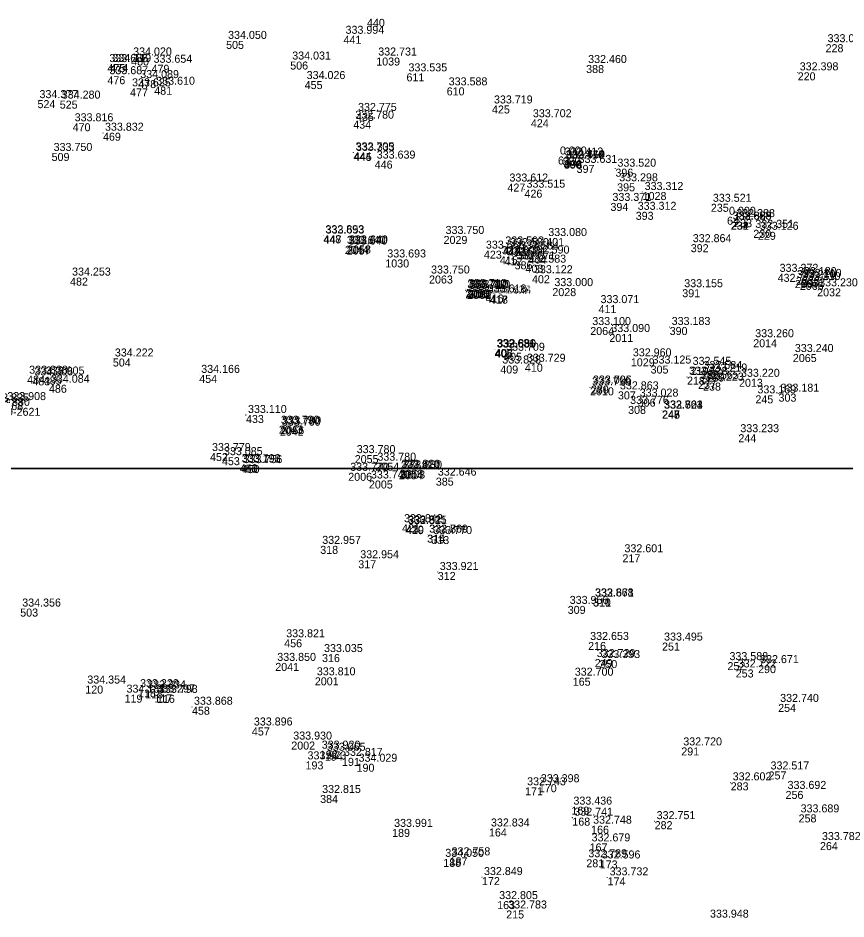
# Model space of a CAD drawing. Extents: x -829398 to -819400, y -1074439 to -1067977.
# Drawn here: x -819793.7 to -819669.5, y -1073067.5 to -1072932.5 of the extents above; entities that cross this region are included whole.
import ezdxf

# ---------------------------------------------------------------- set-up
doc = ezdxf.new("R2010")
doc.units = 0
for name, color, linetype in [('Vrstva 60', 7, 'Continuous'), ('Vrstva 61', 7, 'Continuous'), ('Čísla bodů_doměření_2012', 7, 'Continuous')]:
    doc.layers.add(name, color=color, linetype=linetype)

# ---------------------------------------------------------------- blocks, each defined once
blk = doc.blocks.new('BOD')
at = {"layer": 'Čísla bodů_doměření_2012'}
for p, q in [((-0.15, 0), (0.15, 0)), ((0, -0.15), (0, 0.15))]:
    blk.add_line(p, q, dxfattribs=at)

msp = doc.modelspace()

# ---------------------------------------------------------------- linework, layer by layer
at = {"layer": 'Vrstva 61'}
for points in [[(-819400, -1072500), (-820100, -1072500), (-820100, -1073000), (-819400, -1073000)], [(-819500, -1073000), (-820200, -1073000), (-820200, -1073500), (-819500, -1073500)]]:
    msp.add_lwpolyline(points, close=True, dxfattribs=at)

# ---------------------------------------------------------------- block references
at = {"layer": 'Vrstva 60', "xscale": 0.010000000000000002, "yscale": 0.010000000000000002}
for p in [(-819741.346, -1072932.627), (-819762.463, -1072935.941), (-819744.858, -1072935.172), (-819672.591, -1072936.433), (-819776.698, -1072938.42), (-819739.955, -1072938.429), (-819780.255, -1072939.412), (-819779.8, -1072939.386), (-819773.639, -1072939.515), (-819752.848, -1072939.032), (-819708.487, -1072939.554), (-819780.249, -1072941.229), (-819735.421, -1072940.802), (-819676.772, -1072940.648), (-819775.633, -1072941.811), (-819750.686, -1072941.956), (-819776.86, -1072943.052), (-819773.234, -1072942.806), (-819729.392, -1072942.904), (-819790.739, -1072944.814), (-819787.397, -1072944.888), (-819742.985, -1072946.734), (-819722.609, -1072945.612), (-819743.397, -1072947.889), (-819716.771, -1072947.68), (-819785.465, -1072948.283), (-819780.917, -1072949.7), (-819788.618, -1072952.733), (-819743.353, -1072952.639), (-819743.3, -1072952.717), (-819712.715, -1072953.265), (-819712.024, -1072953.42), (-819740.183, -1072953.876), (-819711.868, -1072953.87), (-819711.807, -1072953.884), (-819711.756, -1072953.81), (-819709.919, -1072954.521), (-819704.098, -1072955.088), (-819720.285, -1072957.317), (-819703.836, -1072957.279), (-819717.73, -1072958.233), (-819700.017, -1072958.584), (-819704.842, -1072960.223), (-819701.058, -1072961.551), (-819689.79, -1072960.351), (-819687.369, -1072962.295), (-819686.828, -1072963.021), (-819686.287, -1072962.646), (-819686.794, -1072963.035), (-819686.775, -1072963.04), (-819683.429, -1072964.253), (-819747.877, -1072965.058), (-819747.839, -1072965.109), (-819729.86, -1072965.17), (-819714.466, -1072965.484), (-819682.74, -1072964.549), (-819744.65, -1072966.66), (-819744.38, -1072966.76), (-819744.32, -1072966.59), (-819720.901, -1072966.742), (-819720.186, -1072966.997), (-819692.806, -1072966.404), (-819723.815, -1072967.371), (-819721.42, -1072968.207), (-819720.727, -1072968.375), (-819718.667, -1072967.497), (-819717.087, -1072968.111), (-819738.597, -1072968.692), (-819719.211, -1072968.97), (-819717.585, -1072969.471), (-819732.04, -1072971.1), (-819716.607, -1072971.06), (-819679.781, -1072970.848), (-819785.854, -1072971.41), (-819677.2, -1072971.78), (-819677.04, -1072971.34), (-819676.46, -1072972.06), (-819676.3, -1072971.61), (-819726.6, -1072973.31), (-819726.53, -1072973.12), (-819726.31, -1072973.41), (-819726.25, -1072973.21), (-819725.98, -1072973.29), (-819713.55, -1072972.99), (-819694.078, -1072973.155), (-819673.86, -1072973.02), (-819723.545, -1072973.945), (-819722.94, -1072974.144), (-819722.882, -1072974.106), (-819706.629, -1072975.537), (-819707.87, -1072978.82), (-819695.967, -1072978.815), (-819705.01, -1072979.87), (-819683.44, -1072980.65), (-819722.198, -1072982.123), (-819722.173, -1072982.212), (-819722.095, -1072982.155), (-819720.785, -1072982.678), (-819677.5, -1072982.87), (-819779.439, -1072983.537), (-819721.356, -1072984.59), (-819717.674, -1072984.324), (-819701.786, -1072983.515), (-819698.823, -1072984.596), (-819692.823, -1072984.788), (-819691.196, -1072985.418), (-819690.43, -1072985.79), (-819792.288, -1072986.117), (-819791.507, -1072986.368), (-819789.796, -1072986.24), (-819766.489, -1072985.996), (-819693.367, -1072986.263), (-819691.703, -1072986.887), (-819690.958, -1072987.149), (-819685.57, -1072986.58), (-819789.021, -1072987.471), (-819707.9, -1072987.86), (-819707.768, -1072987.595), (-819707.768, -1072987.596), (-819703.72, -1072988.466), (-819700.757, -1072989.547), (-819683.111, -1072989.062), (-819679.647, -1072988.808), (-819702.198, -1072990.647), (-819697.121, -1072991.364), (-819697.12, -1072991.316), (-819697.084, -1072991.342), (-819759.48, -1072992.005), (-819754.55, -1072993.61), (-819754.4, -1072993.92), (-819754.32, -1072993.7), (-819685.669, -1072994.884), (-819764.874, -1072997.708), (-819743.18, -1072998.02), (-819763.086, -1072998.326), (-819760.403, -1072999.435), (-819760.394, -1072999.379), (-819740.08, -1072999.15), (-819760.133, -1072999.517), (-819744.15, -1073000.67), (-819744.15, -1073000.67), (-819736.56, -1073000.44), (-819736.56, -1073000.44), (-819736.48, -1073000.22), (-819736.48, -1073000.22), (-819736.19, -1073000.32), (-819736.19, -1073000.32), (-819741.05, -1073001.82), (-819741.05, -1073001.82), (-819731.024, -1073001.391), (-819731.024, -1073001.391), (-819736.085, -1073008.37), (-819736.085, -1073008.37), (-819735.503, -1073008.571), (-819735.503, -1073008.571), (-819735.482, -1073008.663), (-819735.482, -1073008.663), (-819732.329, -1073009.933), (-819732.329, -1073009.933), (-819732.299, -1073009.952), (-819732.299, -1073009.952), (-819731.693, -1073010.151), (-819731.693, -1073010.151), (-819748.351, -1073011.623), (-819748.351, -1073011.623), (-819703.042, -1073012.879), (-819703.042, -1073012.879), (-819742.65, -1073013.778), (-819742.65, -1073013.778), (-819730.733, -1073015.538), (-819730.733, -1073015.538), (-819707.48, -1073019.493), (-819707.48, -1073019.493), (-819707.43, -1073019.513), (-819707.43, -1073019.513), (-819793.321, -1073021.015), (-819793.321, -1073021.015), (-819711.249, -1073020.618), (-819711.249, -1073020.618), (-819753.75, -1073025.621), (-819753.75, -1073025.621), (-819708.184, -1073026.021), (-819708.184, -1073026.021), (-819697.105, -1073026.114), (-819697.105, -1073026.114), (-819748.079, -1073027.837), (-819748.079, -1073027.837), (-819755.09, -1073029.16), (-819755.09, -1073029.16), (-819707.202, -1073028.587), (-819707.202, -1073028.587), (-819706.499, -1073028.733), (-819706.499, -1073028.733), (-819687.304, -1073029.045), (-819687.304, -1073029.045), (-819686.064, -1073030.141), (-819686.064, -1073030.141), (-819682.712, -1073029.494), (-819682.712, -1073029.494), (-819749.16, -1073031.32), (-819749.16, -1073031.32), (-819710.497, -1073031.378), (-819710.497, -1073031.378), (-819783.568, -1073032.556), (-819783.568, -1073032.556), (-819775.659, -1073033.101), (-819775.659, -1073033.101), (-819777.685, -1073033.916), (-819777.685, -1073033.916), (-819774.586, -1073033.288), (-819774.586, -1073033.288), (-819773.225, -1073033.893), (-819773.225, -1073033.893), (-819772.827, -1073033.95), (-819772.827, -1073033.95), (-819767.574, -1073035.732), (-819767.574, -1073035.732), (-819679.701, -1073035.307), (-819679.701, -1073035.307), (-819758.599, -1073038.841), (-819758.599, -1073038.841), (-819752.69, -1073040.95), (-819752.69, -1073040.95), (-819748.43, -1073042.311), (-819748.43, -1073042.311), (-819747.654, -1073042.624), (-819747.654, -1073042.624), (-819694.225, -1073041.828), (-819694.225, -1073041.828), (-819750.557, -1073043.919), (-819750.557, -1073043.919), (-819745.088, -1073043.395), (-819745.088, -1073043.395), (-819742.904, -1073044.272), (-819742.904, -1073044.272), (-819681.145, -1073045.428), (-819681.145, -1073045.428), (-819717.636, -1073047.805), (-819717.636, -1073047.805), (-819715.58, -1073047.342), (-819715.58, -1073047.342), (-819686.821, -1073047.063), (-819686.821, -1073047.063), (-819748.364, -1073048.957), (-819748.364, -1073048.957), (-819678.592, -1073048.348), (-819678.592, -1073048.348), (-819710.691, -1073050.7), (-819710.691, -1073050.7), (-819676.638, -1073051.866), (-819676.638, -1073051.866), (-819710.558, -1073052.355), (-819710.558, -1073052.355), (-819698.217, -1073052.88), (-819698.217, -1073052.88), (-819737.574, -1073054.039), (-819737.574, -1073054.039), (-819723.055, -1073053.977), (-819723.055, -1073053.977), (-819707.743, -1073053.56), (-819707.743, -1073053.56), (-819673.434, -1073056.016), (-819673.434, -1073056.016), (-819707.97, -1073056.213), (-819707.97, -1073056.213), (-819729.899, -1073058.527), (-819729.899, -1073058.527), (-819728.958, -1073058.296), (-819728.958, -1073058.296), (-819708.456, -1073058.591), (-819708.456, -1073058.591), (-819706.453, -1073058.769), (-819706.453, -1073058.769), (-819724.1, -1073061.259), (-819724.1, -1073061.259), (-819705.267, -1073061.299), (-819705.267, -1073061.299), (-819721.825, -1073064.86), (-819721.825, -1073064.86), (-819720.469, -1073066.267), (-819720.469, -1073066.267)]:
    msp.add_blockref('BOD', p, dxfattribs=at)

# ---------------------------------------------------------------- texts
at = {"layer": 'Vrstva 60'}
for s, p in [('440', (-819741.346, -1072933.827)), ('505', (-819762.463, -1072937.141)), ('441', (-819744.858, -1072936.372)), ('228', (-819672.591, -1072937.633)), ('480', (-819776.698, -1072939.62)), ('1039', (-819739.955, -1072939.629)), ('475', (-819780.255, -1072940.612)), ('474', (-819779.8, -1072940.586)), ('479', (-819773.639, -1072940.715)), ('506', (-819752.848, -1072940.232)), ('388', (-819708.487, -1072940.754)), ('476', (-819780.249, -1072942.429)), ('611', (-819735.421, -1072942.002)), ('220', (-819676.772, -1072941.848)), ('478', (-819775.633, -1072943.011)), ('455', (-819750.686, -1072943.156)), ('477', (-819776.86, -1072944.252)), ('481', (-819773.234, -1072944.006)), ('610', (-819729.392, -1072944.104)), ('524', (-819790.739, -1072946.014)), ('525', (-819787.397, -1072946.088)), ('435', (-819742.985, -1072947.934)), ('425', (-819722.609, -1072946.812)), ('434', (-819743.397, -1072949.089)), ('424', (-819716.771, -1072948.88)), ('470', (-819785.465, -1072949.483)), ('469', (-819780.917, -1072950.9)), ('509', (-819788.618, -1072953.933)), ('444', (-819743.353, -1072953.839)), ('445', (-819743.3, -1072953.917)), ('63', (-819712.715, -1072954.465)), ('389', (-819712.024, -1072954.62)), ('446', (-819740.183, -1072955.076)), ('400', (-819711.868, -1072955.07)), ('399', (-819711.807, -1072955.084)), ('398', (-819711.756, -1072955.01)), ('397', (-819709.919, -1072955.721)), ('396', (-819704.098, -1072956.288)), ('427', (-819720.285, -1072958.517)), ('395', (-819703.836, -1072958.479)), ('426', (-819717.73, -1072959.433)), ('1028', (-819700.017, -1072959.784)), ('394', (-819704.842, -1072961.423)), ('393', (-819701.058, -1072962.751)), ('235', (-819689.79, -1072961.551)), ('64', (-819687.369, -1072963.495)), ('234', (-819686.828, -1072964.221)), ('232', (-819686.794, -1072964.235)), ('231', (-819686.775, -1072964.24)), ('233', (-819686.287, -1072963.846)), ('230', (-819683.429, -1072965.453)), ('448', (-819747.877, -1072966.258)), ('447', (-819747.839, -1072966.309)), ('2029', (-819729.86, -1072966.37)), ('401', (-819714.466, -1072966.684)), ('229', (-819682.74, -1072965.749)), ('2044', (-819744.65, -1072967.86)), ('2057', (-819744.38, -1072967.96)), ('2058', (-819744.32, -1072967.79)), ('414', (-819720.901, -1072967.942)), ('413', (-819720.186, -1072968.197)), ('392', (-819692.806, -1072967.604)), ('423', (-819723.815, -1072968.571)), ('415', (-819721.42, -1072969.407)), ('412', (-819720.727, -1072969.575)), ('387', (-819718.667, -1072968.697)), ('404', (-819717.087, -1072969.311)), ('1030', (-819738.597, -1072969.892)), ('386', (-819719.211, -1072970.17)), ('403', (-819717.585, -1072970.671)), ('2063', (-819732.04, -1072972.3)), ('402', (-819716.607, -1072972.26)), ('432', (-819679.781, -1072972.048)), ('482', (-819785.854, -1072972.61)), ('2067', (-819677.2, -1072972.98)), ('2030', (-819677.04, -1072972.54)), ('2066', (-819676.46, -1072973.26)), ('2031', (-819676.3, -1072972.81)), ('2060', (-819726.6, -1072974.51)), ('2059', (-819726.53, -1072974.32)), ('2061', (-819726.31, -1072974.61)), ('2062', (-819726.25, -1072974.41)), ('2007', (-819725.98, -1072974.49)), ('2028', (-819713.55, -1072974.19)), ('391', (-819694.078, -1072974.355)), ('2032', (-819673.86, -1072974.22)), ('416', (-819723.545, -1072975.145)), ('417', (-819722.94, -1072975.344)), ('418', (-819722.882, -1072975.306)), ('411', (-819706.629, -1072976.737)), ('2064', (-819707.87, -1072980.02)), ('390', (-819695.967, -1072980.015)), ('2011', (-819705.01, -1072981.07)), ('2014', (-819683.44, -1072981.85)), ('408', (-819722.198, -1072983.323)), ('406', (-819722.173, -1072983.412)), ('407', (-819722.095, -1072983.355)), ('405', (-819720.785, -1072983.878)), ('2065', (-819677.5, -1072984.07)), ('504', (-819779.439, -1072984.737)), ('409', (-819721.356, -1072985.79)), ('410', (-819717.674, -1072985.524)), ('1029', (-819701.786, -1072984.715)), ('305', (-819698.823, -1072985.796)), ('219', (-819692.823, -1072985.988)), ('236', (-819691.196, -1072986.618)), ('239', (-819690.43, -1072986.99)), ('484', (-819792.288, -1072987.317)), ('483', (-819791.507, -1072987.568)), ('485', (-819789.796, -1072987.44)), ('454', (-819766.489, -1072987.196)), ('218', (-819693.367, -1072987.463)), ('237', (-819691.703, -1072988.087)), ('238', (-819690.958, -1072988.349)), ('2013', (-819685.57, -1072987.78)), ('486', (-819789.021, -1072988.671)), ('2010', (-819707.9, -1072989.06)), ('280', (-819707.768, -1072988.795)), ('279', (-819707.768, -1072988.796)), ('307', (-819703.72, -1072989.666)), ('306', (-819700.757, -1072990.747)), ('245', (-819683.111, -1072990.262)), ('303', (-819679.647, -1072990.008)), ('5799-2621', (-819797.973, -1072992.128)), ('468', (-819795.563, -1072991.27)), ('308', (-819702.198, -1072991.847)), ('248', (-819697.121, -1072992.564)), ('247', (-819697.12, -1072992.516)), ('246', (-819697.084, -1072992.542)), ('433', (-819759.48, -1072993.205)), ('2043', (-819754.55, -1072994.81)), ('2042', (-819754.4, -1072995.12)), ('2056', (-819754.32, -1072994.9)), ('244', (-819685.669, -1072996.084)), ('452', (-819764.874, -1072998.908)), ('2055', (-819743.18, -1072999.22)), ('453', (-819763.086, -1072999.526)), ('451', (-819760.403, -1073000.635)), ('449', (-819760.394, -1073000.579)), ('2054', (-819740.08, -1073000.35)), ('2054', (-819740.08, -1073000.35)), ('450', (-819760.133, -1073000.717)), ('2006', (-819744.15, -1073001.87)), ('2004', (-819736.56, -1073001.64)), ('2053', (-819736.48, -1073001.42)), ('2003', (-819736.19, -1073001.52)), ('2005', (-819741.05, -1073003.02)), ('385', (-819731.024, -1073002.591)), ('421', (-819736.085, -1073009.57)), ('420', (-819735.503, -1073009.771)), ('419', (-819735.482, -1073009.863)), ('315', (-819732.329, -1073011.133)), ('314', (-819732.299, -1073011.152)), ('313', (-819731.693, -1073011.351)), ('318', (-819748.351, -1073012.823)), ('217', (-819703.042, -1073014.079)), ('317', (-819742.65, -1073014.978)), ('312', (-819730.733, -1073016.738)), ('310', (-819707.48, -1073020.693)), ('311', (-819707.43, -1073020.713)), ('503', (-819793.321, -1073022.215)), ('309', (-819711.249, -1073021.818)), ('456', (-819753.75, -1073026.821)), ('216', (-819708.184, -1073027.221)), ('251', (-819697.105, -1073027.314)), ('316', (-819748.079, -1073029.037)), ('2041', (-819755.09, -1073030.36)), ('249', (-819707.202, -1073029.787)), ('250', (-819706.499, -1073029.933)), ('252', (-819687.304, -1073030.245)), ('253', (-819686.064, -1073031.341)), ('290', (-819682.712, -1073030.694)), ('2001', (-819749.16, -1073032.52)), ('165', (-819710.497, -1073032.578)), ('120', (-819783.568, -1073033.756)), ('118', (-819775.659, -1073034.301)), ('119', (-819777.685, -1073035.116)), ('115', (-819774.586, -1073034.488)), ('117', (-819773.225, -1073035.093)), ('116', (-819772.827, -1073035.15)), ('458', (-819767.574, -1073036.932)), ('254', (-819679.701, -1073036.507)), ('457', (-819758.599, -1073040.041)), ('2002', (-819752.69, -1073042.15)), ('192', (-819748.43, -1073043.511)), ('194', (-819747.654, -1073043.824)), ('291', (-819694.225, -1073043.028)), ('193', (-819750.557, -1073045.119)), ('191', (-819745.088, -1073044.595)), ('190', (-819742.904, -1073045.472)), ('257', (-819681.145, -1073046.628)), ('171', (-819717.636, -1073049.005)), ('170', (-819715.58, -1073048.542)), ('283', (-819686.821, -1073048.263)), ('384', (-819748.364, -1073050.157)), ('256', (-819678.592, -1073049.548)), ('169', (-819710.691, -1073051.9)), ('258', (-819676.638, -1073053.066)), ('168', (-819710.558, -1073053.555)), ('282', (-819698.217, -1073054.08)), ('189', (-819737.574, -1073055.239)), ('164', (-819723.055, -1073055.177)), ('166', (-819707.743, -1073054.76)), ('167', (-819707.97, -1073057.413)), ('264', (-819673.434, -1073057.216)), ('188', (-819729.899, -1073059.727)), ('187', (-819728.958, -1073059.496)), ('281', (-819708.456, -1073059.791)), ('173', (-819706.453, -1073059.969)), ('172', (-819724.1, -1073062.459)), ('174', (-819705.267, -1073062.499)), ('163', (-819721.825, -1073066.06)), ('215', (-819720.469, -1073067.467))]:
    msp.add_text(s, height=1.2, dxfattribs=at).set_placement(p)
at = {"layer": 'Vrstva 61'}
for s, p in [('334.050', (-819762.163, -1072935.641)), ('333.994', (-819744.558, -1072934.872)), ('333.058', (-819672.291, -1072936.133)), ('334.020', (-819776.398, -1072938.12)), ('332.731', (-819739.655, -1072938.129)), ('333.686', (-819779.955, -1072939.112)), ('334.119', (-819779.5, -1072939.086)), ('333.654', (-819773.339, -1072939.215)), ('334.031', (-819752.548, -1072938.732)), ('332.460', (-819708.187, -1072939.254)), ('333.687', (-819779.949, -1072940.929)), ('333.535', (-819735.121, -1072940.502)), ('332.398', (-819676.472, -1072940.348)), ('334.089', (-819775.333, -1072941.511)), ('333.610', (-819772.934, -1072942.506)), ('334.026', (-819750.386, -1072941.656)), ('333.588', (-819729.092, -1072942.604)), ('333.625', (-819776.56, -1072942.752)), ('334.377', (-819790.439, -1072944.514)), ('334.280', (-819787.097, -1072944.588)), ('333.719', (-819722.309, -1072945.312)), ('332.775', (-819742.685, -1072946.434)), ('333.816', (-819785.165, -1072947.983)), ('332.780', (-819743.097, -1072947.589)), ('333.702', (-819716.471, -1072947.38)), ('333.832', (-819780.617, -1072949.4)), ('333.750', (-819788.318, -1072952.433)), ('332.705', (-819743.053, -1072952.339)), ('333.333', (-819743, -1072952.417)), ('0.000', (-819712.415, -1072952.965)), ('332.412', (-819711.724, -1072953.12)), ('333.639', (-819739.883, -1072953.576)), ('332.475', (-819711.568, -1072953.57)), ('332.754', (-819711.507, -1072953.584)), ('333.619', (-819711.456, -1072953.51)), ('333.631', (-819709.619, -1072954.221)), ('333.520', (-819703.798, -1072954.788)), ('333.612', (-819719.985, -1072957.017)), ('333.298', (-819703.536, -1072956.979)), ('333.515', (-819717.43, -1072957.933)), ('333.312', (-819699.717, -1072958.284)), ('333.371', (-819704.542, -1072959.923)), ('333.521', (-819689.49, -1072960.051)), ('333.312', (-819700.758, -1072961.251)), ('0.000', (-819687.069, -1072961.995)), ('333.658', (-819686.528, -1072962.721)), ('332.825', (-819686.494, -1072962.735)), ('332.389', (-819686.475, -1072962.74)), ('332.388', (-819685.987, -1072962.346)), ('332.351', (-819683.129, -1072963.953)), ('332.893', (-819747.577, -1072964.758)), ('333.653', (-819747.539, -1072964.809)), ('333.750', (-819729.56, -1072964.87)), ('333.080', (-819714.166, -1072965.184)), ('333.126', (-819682.44, -1072964.249)), ('333.640', (-819744.35, -1072966.36)), ('333.640', (-819744.08, -1072966.46)), ('333.640', (-819744.02, -1072966.29)), ('333.592', (-819720.601, -1072966.442)), ('332.580', (-819719.886, -1072966.697)), ('332.864', (-819692.506, -1072966.104)), ('333.666', (-819723.515, -1072967.071)), ('333.603', (-819721.12, -1072967.907)), ('332.574', (-819720.427, -1072968.075)), ('332.564', (-819718.367, -1072967.197)), ('332.590', (-819716.787, -1072967.811)), ('333.693', (-819738.297, -1072968.392)), ('332.571', (-819718.911, -1072968.67)), ('332.583', (-819717.285, -1072969.171)), ('333.750', (-819731.74, -1072970.8)), ('333.122', (-819716.307, -1072970.76)), ('333.272', (-819679.481, -1072970.548)), ('334.253', (-819785.554, -1072971.11)), ('333.210', (-819676.9, -1072971.48)), ('333.180', (-819676.74, -1072971.04)), ('333.210', (-819676.16, -1072971.76)), ('333.210', (-819676, -1072971.31)), ('333.710', (-819726.3, -1072973.01)), ('333.710', (-819726.23, -1072972.82)), ('333.710', (-819726.01, -1072973.11)), ('333.710', (-819725.95, -1072972.91)), ('333.710', (-819725.68, -1072972.99)), ('333.618', (-819723.245, -1072973.645)), ('333.000', (-819713.25, -1072972.69)), ('333.155', (-819693.778, -1072972.855)), ('333.230', (-819673.56, -1072972.72)), ('333.712', (-819722.64, -1072973.844)), ('332.538', (-819722.582, -1072973.806)), ('333.071', (-819706.329, -1072975.237)), ('333.100', (-819707.57, -1072978.52)), ('333.183', (-819695.667, -1072978.515)), ('333.090', (-819704.71, -1072979.57)), ('333.260', (-819683.14, -1072980.35)), ('332.631', (-819721.898, -1072981.823)), ('333.686', (-819721.873, -1072981.912)), ('332.880', (-819721.795, -1072981.855)), ('333.709', (-819720.485, -1072982.378)), ('333.240', (-819677.2, -1072982.57)), ('334.222', (-819779.139, -1072983.237)), ('333.828', (-819721.056, -1072984.29)), ('333.729', (-819717.374, -1072984.024)), ('332.960', (-819701.486, -1072983.215)), ('333.125', (-819698.523, -1072984.296)), ('332.545', (-819692.523, -1072984.488)), ('333.838', (-819791.988, -1072985.817)), ('334.166', (-819766.189, -1072985.696)), ('332.584', (-819690.896, -1072985.118)), ('333.219', (-819690.13, -1072985.49)), ('334.306', (-819791.207, -1072986.068)), ('333.905', (-819789.496, -1072985.94)), ('334.084', (-819788.721, -1072987.171)), ('332.528', (-819693.067, -1072985.963)), ('332.565', (-819691.403, -1072986.587)), ('333.223', (-819690.658, -1072986.849)), ('333.220', (-819685.27, -1072986.28)), ('333.710', (-819707.6, -1072987.56)), ('333.026', (-819707.468, -1072987.295)), ('333.705', (-819707.468, -1072987.296)), ('332.863', (-819703.42, -1072988.166)), ('333.181', (-819679.347, -1072988.508)), ('333.908', (-819795.263, -1072989.77)), ('333.028', (-819700.457, -1072989.247)), ('333.169', (-819682.811, -1072988.762)), ('333.835', (-819797.812, -1072989.979)), ('333.880', (-819797.673, -1072990.628)), ('333.776', (-819701.898, -1072990.347)), ('333.723', (-819696.821, -1072991.064)), ('332.861', (-819696.82, -1072991.016)), ('332.504', (-819696.784, -1072991.042)), ('333.110', (-819759.18, -1072991.705)), ('333.790', (-819754.25, -1072993.31)), ('333.760', (-819754.1, -1072993.62)), ('333.780', (-819754.02, -1072993.4)), ('333.233', (-819685.369, -1072994.584)), ('333.779', (-819764.574, -1072997.408)), ('333.780', (-819742.88, -1072997.72)), ('333.085', (-819762.786, -1072998.026)), ('333.195', (-819760.103, -1072999.135)), ('333.792', (-819760.094, -1072999.079)), ('333.756', (-819759.833, -1072999.217)), ('333.780', (-819739.78, -1072998.85)), ('333.770', (-819743.85, -1073000.37)), ('333.770', (-819743.85, -1073000.37)), ('333.810', (-819736.26, -1073000.14)), ('333.810', (-819736.26, -1073000.14)), ('333.820', (-819736.18, -1072999.92)), ('333.830', (-819735.89, -1073000.02)), ('333.830', (-819735.89, -1073000.02)), ('333.740', (-819740.75, -1073001.52)), ('332.646', (-819730.724, -1073001.091)), ('332.646', (-819730.724, -1073001.091)), ('333.842', (-819735.785, -1073008.07)), ('333.825', (-819735.203, -1073008.271)), ('332.811', (-819735.182, -1073008.363)), ('332.760', (-819732.029, -1073009.633)), ('333.809', (-819731.999, -1073009.652)), ('333.770', (-819731.393, -1073009.851)), ('332.957', (-819748.051, -1073011.323)), ('332.601', (-819702.742, -1073012.579)), ('332.954', (-819742.35, -1073013.478)), ('333.921', (-819730.433, -1073015.238)), ('333.868', (-819707.18, -1073019.193)), ('332.671', (-819707.13, -1073019.213)), ('334.356', (-819793.021, -1073020.715)), ('333.956', (-819710.949, -1073020.318)), ('333.821', (-819753.45, -1073025.321)), ('332.653', (-819707.884, -1073025.721)), ('333.495', (-819696.805, -1073025.814)), ('333.035', (-819747.779, -1073027.537)), ('333.850', (-819754.79, -1073028.86)), ('332.729', (-819706.902, -1073028.287)), ('333.393', (-819706.199, -1073028.433)), ('333.588', (-819687.004, -1073028.745)), ('332.722', (-819685.764, -1073029.841)), ('332.671', (-819682.412, -1073029.194)), ('333.810', (-819748.86, -1073031.02)), ('332.700', (-819710.197, -1073031.078)), ('334.354', (-819783.268, -1073032.256)), ('333.228', (-819775.359, -1073032.801)), ('333.334', (-819774.286, -1073032.988)), ('334.181', (-819777.385, -1073033.616)), ('333.297', (-819772.925, -1073033.593)), ('333.798', (-819772.527, -1073033.65)), ('333.868', (-819767.274, -1073035.432)), ('332.740', (-819679.401, -1073035.007)), ('333.896', (-819758.299, -1073038.541)), ('333.930', (-819752.39, -1073040.65)), ('333.920', (-819748.13, -1073042.011)), ('333.065', (-819747.354, -1073042.324)), ('332.720', (-819693.925, -1073041.528)), ('333.973', (-819750.257, -1073043.619)), ('332.817', (-819744.788, -1073043.095)), ('334.029', (-819742.604, -1073043.972)), ('332.517', (-819680.845, -1073045.128)), ('332.743', (-819717.336, -1073047.505)), ('333.398', (-819715.28, -1073047.042)), ('332.602', (-819686.521, -1073046.763)), ('332.815', (-819748.064, -1073048.657)), ('333.692', (-819678.292, -1073048.048)), ('333.436', (-819710.391, -1073050.4)), ('333.689', (-819676.338, -1073051.566)), ('332.741', (-819710.258, -1073052.055)), ('332.748', (-819707.443, -1073053.26)), ('332.751', (-819697.917, -1073052.58)), ('333.991', (-819737.274, -1073053.739)), ('332.834', (-819722.755, -1073053.677)), ('332.679', (-819707.67, -1073055.913)), ('333.782', (-819673.134, -1073055.716)), ('334.050', (-819729.599, -1073058.227)), ('332.758', (-819728.658, -1073057.996)), ('332.789', (-819708.156, -1073058.291)), ('332.596', (-819706.153, -1073058.469)), ('332.849', (-819723.8, -1073060.959)), ('333.732', (-819704.967, -1073060.999)), ('332.805', (-819721.525, -1073064.56)), ('332.783', (-819720.169, -1073065.967)), ('333.948', (-819689.919, -1073067.338))]:
    msp.add_text(s, height=1.2, dxfattribs=at).set_placement(p)

doc.saveas('drawing.dxf')
